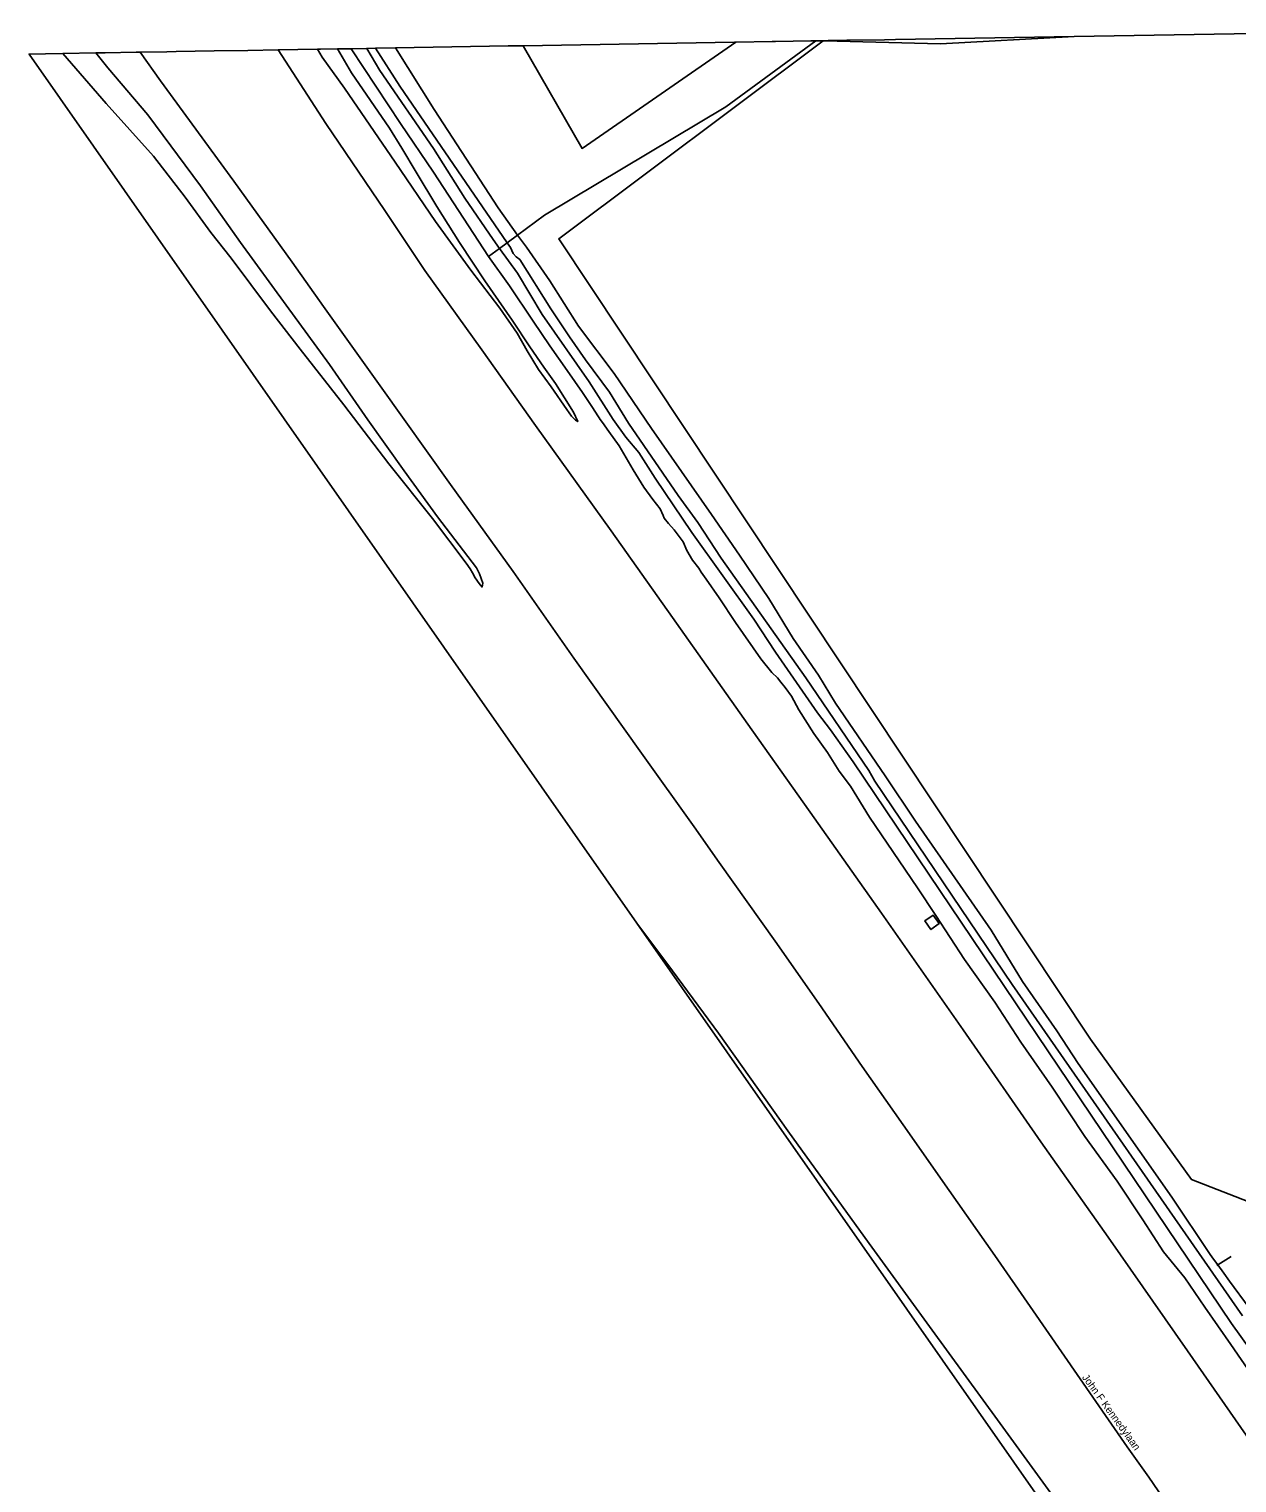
# Model space of a CAD drawing. Extents: x 161385 to 162589, y 388479 to 389756.
# Drawn here: x 161384.7 to 161547.5, y 389543.3 to 389739.2 of the extents above; entities that cross this region are included whole.
import ezdxf

# ---------------------------------------------------------------- set-up
doc = ezdxf.new("R2010")
doc.units = 0
for name, color, linetype in [('IMGEO_Berm_groen', 7, 'Continuous'), ('IMGEO_Bouwland', 7, 'Continuous'), ('IMGEO_Duiker', 7, 'Continuous'), ('IMGEO_Grasland_overig', 7, 'Continuous'), ('IMGEO_Groenvoorziening', 7, 'Continuous'), ('IMGEO_Loofbos', 7, 'Continuous'), ('IMGEO_Oever', 7, 'Continuous'), ('IMGEO_Openbare_ruimte_label', 7, 'Continuous'), ('IMGEO_Rijbaan_autoweg', 7, 'Continuous'), ('IMGEO_Sloot', 7, 'Continuous'), ('IMGEO_Terreindeel_gesloten', 7, 'Continuous'), ('IMGEO_Waterloop', 7, 'Continuous')]:
    doc.layers.add(name, color=color, linetype=linetype)

msp = doc.modelspace()

# ---------------------------------------------------------------- linework, layer by layer
at = {"layer": 'IMGEO_Berm_groen'}
for points in [[(161541.9, 389534.86), (161535.61, 389544.06), (161532.71, 389548.16), (161519.61, 389567.09), (161514.87, 389573.94), (161508.72, 389582.71), (161502.51, 389591.56), (161497, 389599.42), (161491.15, 389607.89), (161485.26, 389616.29), (161477.74, 389626.88), (161474.36, 389631.68), (161467.26, 389641.62), (161458.15, 389654.42), (161449.95, 389666.11), (161441.53, 389677.82), (161432.05, 389691.12), (161424.41, 389701.8), (161420.18, 389707.76), (161412.3, 389718.71), (161402.44, 389732.19), (161399.68, 389736.06), (161399.16, 389736.05), (161394.99, 389735.98), (161394.09, 389735.97), (161393.7, 389735.96), (161395.33, 389733.96), (161400.71, 389727.64), (161407.81, 389718.07), (161413.22, 389710.41), (161419.38, 389702), (161425.2, 389694), (161430.37, 389686.52), (161435.26, 389679.67), (161439.75, 389673.45), (161445.04, 389666.6), (161445.42, 389665.79), (161445.85, 389664.54), (161445.77, 389664.01), (161445.39, 389664.46), (161444.83, 389665.25), (161444.48, 389665.92), (161444.18, 389666.46), (161443.63, 389667.23), (161439.07, 389673.24), (161433.2, 389680.6), (161427.13, 389688.55), (161421.26, 389696.04), (161417.27, 389701.23), (161411.95, 389708.33), (161409.23, 389711.76), (161405.76, 389716.55), (161401.48, 389722.05), (161395.13, 389729.14), (161389.29, 389735.89), (161386.95, 389735.85), (161384.73, 389735.81), (161466.61, 389618.74), (161471.45, 389612.28), (161477.61, 389603.91), (161486.97, 389590.73), (161497.93, 389575.54), (161506.43, 389563.89), (161515.21, 389551.81), (161522.76, 389541.44)], [(161550.85, 389555.87), (161546.65, 389561.93), (161543.15, 389566.99), (161540.45, 389570.93), (161537.58, 389574.43), (161534.82, 389578.75), (161531.34, 389583.94), (161526.99, 389589.98), (161522.59, 389596.62), (161518.39, 389602.68), (161514.85, 389608.07), (161510.78, 389613.84), (161506.91, 389619.75), (161504.43, 389623.46), (161501.98, 389627.1), (161497.97, 389632.99), (161495.4, 389637.19), (161493.89, 389639.2), (161492.34, 389641.73), (161490.48, 389644.25), (161488.45, 389647.47), (161487.46, 389649.29), (161486.6, 389650.48), (161486.05, 389651.21), (161485.59, 389651.75), (161484.8, 389652.47), (161483.33, 389654.31), (161479.93, 389659.21), (161477.73, 389662.53), (161475.97, 389665.08), (161475.3, 389666), (161474.99, 389666.56), (161474.13, 389667.61), (161473.37, 389668.92), (161472.85, 389670.08), (161471.64, 389671.7), (161470.88, 389672.58), (161470.29, 389673.3), (161470.18, 389673.66), (161469.75, 389674.54), (161468.8, 389675.82), (161467.56, 389677.48), (161466.12, 389679.81), (161464.26, 389683.01), (161462.84, 389684.96), (161462, 389686.17), (161461.67, 389686.6), (161461.53, 389686.78), (161460.87, 389687.82), (161460.72, 389688.05), (161459.32, 389690.23), (161457.23, 389693.16), (161454.91, 389696.51), (161452.65, 389699.83), (161449.48, 389704.59), (161446.65, 389708.55), (161439.23, 389719.92), (161434.79, 389726.45), (161428.15, 389736.54), (161427.95, 389736.54), (161426.29, 389736.51), (161428.19, 389733.29), (161433.28, 389725.82), (161434.94, 389723.14), (161436.9, 389719.89), (161439.67, 389715.29), (161442.74, 389710.43), (161446.15, 389705.27), (161449.84, 389699.98), (161452.2, 389696.39), (161454.08, 389693.64), (161455.65, 389691.43), (161458.09, 389687.58), (161458.67, 389686.29), (161458.35, 389686.5), (161457.8, 389687.04), (161457.2, 389687.94), (161455.1, 389690.98), (161453.39, 389693.32), (161451.84, 389695.85), (161450.49, 389698.23), (161448.18, 389701.59), (161444.25, 389706.71), (161439.48, 389713.27), (161434.06, 389721.23), (161427.21, 389731.23), (161424.24, 389735.41), (161423.58, 389736.47), (161418.3, 389736.38), (161424.71, 389726.46), (161432.65, 389714.74), (161438.06, 389706.64), (161445.72, 389695.97), (161452.97, 389685.76), (161463.17, 389671.58), (161471.43, 389659.92), (161482.13, 389644.75), (161489.96, 389633.69), (161499.61, 389620.08), (161510.58, 389604.35), (161521.06, 389589.26), (161530.13, 389576.42), (161540.82, 389561.12), (161552.34, 389544.55)]]:
    msp.add_lwpolyline(points, dxfattribs=at)
msp.add_lwpolyline([(161507.36, 389618.66), (161506.25, 389617.86), (161505.43, 389619.01), (161506.55, 389619.8)], close=True, dxfattribs=at)
at = {"layer": 'IMGEO_Bouwland'}
msp.add_lwpolyline([(161479.95, 389737.41), (161459.25, 389723.11), (161451.31, 389736.93), (161479.8, 389737.41)], close=True, dxfattribs=at)
at = {"layer": 'IMGEO_Duiker'}
msp.add_lwpolyline([(161546.72, 389573.82), (161544.9, 389572.67), (161544.79, 389572.6)], dxfattribs=at)
at = {"layer": 'IMGEO_Grasland_overig'}
for points in [[(161393.7, 389735.96), (161389.29, 389735.89), (161395.13, 389729.14), (161401.48, 389722.05), (161405.76, 389716.55), (161409.23, 389711.76), (161411.95, 389708.33), (161417.27, 389701.23), (161421.26, 389696.04), (161427.13, 389688.55), (161433.2, 389680.6), (161439.07, 389673.24), (161443.63, 389667.23), (161444.18, 389666.46), (161444.48, 389665.92), (161444.83, 389665.25), (161445.39, 389664.46), (161445.77, 389664.01), (161445.85, 389664.54), (161445.42, 389665.79), (161445.04, 389666.6), (161439.75, 389673.45), (161435.26, 389679.67), (161430.37, 389686.52), (161425.2, 389694), (161419.38, 389702), (161413.22, 389710.41), (161407.81, 389718.07), (161400.71, 389727.64), (161395.33, 389733.96)], [(161426.29, 389736.51), (161424, 389736.47), (161423.58, 389736.47), (161424.24, 389735.41), (161427.21, 389731.23), (161434.06, 389721.23), (161439.48, 389713.27), (161444.25, 389706.71), (161448.18, 389701.59), (161450.49, 389698.23), (161451.84, 389695.85), (161453.39, 389693.32), (161455.1, 389690.98), (161457.2, 389687.94), (161457.8, 389687.04), (161458.35, 389686.5), (161458.67, 389686.29), (161458.09, 389687.58), (161455.65, 389691.43), (161454.08, 389693.64), (161452.2, 389696.39), (161449.84, 389699.98), (161446.15, 389705.27), (161442.74, 389710.43), (161439.67, 389715.29), (161436.9, 389719.89), (161434.94, 389723.14), (161433.28, 389725.82), (161428.19, 389733.29)]]:
    msp.add_lwpolyline(points, close=True, dxfattribs=at)
at = {"layer": 'IMGEO_Groenvoorziening'}
for points in [[(161479.95, 389737.41), (161484.88, 389737.5), (161485.31, 389737.51), (161490.08, 389737.59), (161490.75, 389737.6), (161478.64, 389728.7), (161454.18, 389714.09), (161450.56, 389711.43), (161447.94, 389715.08), (161439.3, 389728.36), (161434.12, 389736.64), (161449.29, 389736.9), (161451.31, 389736.93), (161459.25, 389723.11)], [(161491.86, 389737.61), (161492.4, 389737.62), (161494.92, 389737.67), (161500, 389737.75), (161501.46, 389737.78), (161525.54, 389738.18), (161507.54, 389737.18)]]:
    msp.add_lwpolyline(points, close=True, dxfattribs=at)
msp.add_lwpolyline([(161554.15, 389579.21), (161541.36, 389584.19), (161527.75, 389603.1), (161456.11, 389710.93), (161491.74, 389737.61), (161490.75, 389737.6), (161478.64, 389728.7), (161454.18, 389714.09), (161450.56, 389711.43), (161451.74, 389709.79), (161454.89, 389705.24), (161458.77, 389699.14), (161463.56, 389692.76), (161468.62, 389685.35), (161476.7, 389673.8), (161480.44, 389668.31), (161484.41, 389662.44), (161487.71, 389657.05), (161491.09, 389652.12), (161493.41, 389648.36), (161500.1, 389638.57), (161504.18, 389632.44), (161514.37, 389617.77), (161518.6, 389610.86), (161523.21, 389604.21), (161526.08, 389599.8), (161538.71, 389581.79), (161543.87, 389574.08), (161544.35, 389573.43), (161544.9, 389572.67), (161545.72, 389571.56), (161546.51, 389570.47), (161551.79, 389563.31)], dxfattribs=at)
at = {"layer": 'IMGEO_Loofbos'}
msp.add_lwpolyline([(161584.85, 389739.18), (161525.54, 389738.18), (161507.54, 389737.18), (161491.86, 389737.61), (161491.74, 389737.61), (161456.11, 389710.93), (161527.75, 389603.1), (161541.36, 389584.19), (161554.15, 389579.21)], dxfattribs=at)
at = {"layer": 'IMGEO_Oever'}
for points in [[(161428.15, 389736.54), (161434.79, 389726.45), (161439.23, 389719.92), (161446.65, 389708.55), (161448.12, 389709.63), (161447.25, 389710.82), (161443.45, 389716.42), (161439.21, 389723.09), (161431.97, 389733.62), (161430.22, 389736.58)], [(161434.12, 389736.64), (161431.41, 389736.6), (161434.7, 389731.47), (161449.14, 389710.38), (161450.56, 389711.43), (161447.94, 389715.08), (161439.3, 389728.36)]]:
    msp.add_lwpolyline(points, close=True, dxfattribs=at)
for points in [[(161551.79, 389563.31), (161546.51, 389570.47), (161545.72, 389571.56), (161544.9, 389572.67), (161544.35, 389573.43), (161543.87, 389574.08), (161538.71, 389581.79), (161526.08, 389599.8), (161523.21, 389604.21), (161518.6, 389610.86), (161514.37, 389617.77), (161504.18, 389632.44), (161500.1, 389638.57), (161493.41, 389648.36), (161491.09, 389652.12), (161487.71, 389657.05), (161484.41, 389662.44), (161480.44, 389668.31), (161476.7, 389673.8), (161468.62, 389685.35), (161463.56, 389692.76), (161458.77, 389699.14), (161454.89, 389705.24), (161451.74, 389709.79), (161450.56, 389711.43), (161449.14, 389710.38), (161449.58, 389709.73), (161449.95, 389708.96), (161450.37, 389708.49), (161450.84, 389708.13), (161455.04, 389701.47), (161457.54, 389697.73), (161459.69, 389694.61), (161462.94, 389690.24), (161465.48, 389686.08), (161472.21, 389676.35), (161474.85, 389672.68), (161478, 389667.88), (161489.42, 389651.78), (161497.88, 389639.28), (161498.7, 389637.87), (161517.22, 389610.46), (161548.23, 389565.82)], [(161552.02, 389557.47), (161546.75, 389564.77), (161495.78, 389640.45), (161492.73, 389644.75), (161490.99, 389647.04), (161485.32, 389655.24), (161482.37, 389659.66), (161474.04, 389671.34), (161469.1, 389678.66), (161466.88, 389682.11), (161465.13, 389684.21), (161463.45, 389686.57), (161460.21, 389691.67), (161453.88, 389700.72), (161450.56, 389706.29), (161448.12, 389709.63), (161446.65, 389708.55), (161449.48, 389704.59), (161452.65, 389699.83), (161454.91, 389696.51), (161457.23, 389693.16), (161459.32, 389690.23), (161460.72, 389688.05), (161460.87, 389687.82), (161461.53, 389686.78), (161461.67, 389686.6), (161462, 389686.17), (161462.84, 389684.96), (161464.26, 389683.01), (161466.12, 389679.81), (161467.56, 389677.48), (161468.8, 389675.82), (161469.75, 389674.54), (161470.18, 389673.66), (161470.29, 389673.3), (161470.88, 389672.58), (161471.64, 389671.7), (161472.85, 389670.08), (161473.37, 389668.92), (161474.13, 389667.61), (161474.99, 389666.56), (161475.3, 389666), (161475.97, 389665.08), (161477.73, 389662.53), (161479.93, 389659.21), (161483.33, 389654.31), (161484.8, 389652.47), (161485.59, 389651.75), (161486.05, 389651.21), (161486.6, 389650.48), (161487.46, 389649.29), (161488.45, 389647.47), (161490.48, 389644.25), (161492.34, 389641.73), (161493.89, 389639.2), (161495.4, 389637.19), (161497.97, 389632.99), (161501.98, 389627.1), (161504.43, 389623.46), (161506.91, 389619.75), (161510.78, 389613.84), (161514.85, 389608.07), (161518.39, 389602.68), (161522.59, 389596.62), (161526.99, 389589.98), (161531.34, 389583.94), (161534.82, 389578.75), (161537.58, 389574.43), (161540.45, 389570.93), (161543.15, 389566.99), (161546.65, 389561.93), (161550.85, 389555.87)]]:
    msp.add_lwpolyline(points, dxfattribs=at)
at = {"layer": 'IMGEO_Rijbaan_autoweg'}
for points in [[(161552.34, 389544.55), (161540.82, 389561.12), (161530.13, 389576.42), (161521.06, 389589.26), (161510.58, 389604.35), (161499.61, 389620.08), (161489.96, 389633.69), (161482.13, 389644.75), (161471.43, 389659.92), (161463.17, 389671.58), (161452.97, 389685.76), (161445.72, 389695.97), (161438.06, 389706.64), (161432.65, 389714.74), (161424.71, 389726.46), (161418.3, 389736.38), (161414.22, 389736.31), (161409.68, 389736.23), (161404.53, 389736.15), (161403.31, 389736.12), (161399.68, 389736.06), (161402.44, 389732.19), (161412.3, 389718.71), (161420.18, 389707.76), (161424.41, 389701.8), (161432.05, 389691.12), (161441.53, 389677.82), (161449.95, 389666.11), (161458.15, 389654.42), (161467.26, 389641.62), (161474.36, 389631.68), (161477.74, 389626.88), (161485.26, 389616.29), (161491.15, 389607.89), (161497, 389599.42), (161502.51, 389591.56), (161508.72, 389582.71), (161514.87, 389573.94), (161519.61, 389567.09), (161532.71, 389548.16), (161535.61, 389544.06), (161541.9, 389534.86)], [(161594.7, 389440.92), (161588.77, 389449.41), (161581.35, 389459.93), (161576.06, 389467.47), (161568.06, 389478.8), (161562.02, 389487.19), (161553.12, 389499.54), (161545.62, 389510.06), (161537.34, 389521.47), (161530.7, 389530.54), (161522.76, 389541.44), (161515.21, 389551.81), (161506.43, 389563.89), (161497.93, 389575.54), (161486.97, 389590.73), (161477.61, 389603.91), (161471.45, 389612.28), (161466.61, 389618.74), (161503, 389566.7), (161575.43, 389463.21), (161603.35, 389423.32)]]:
    msp.add_lwpolyline(points, dxfattribs=at)
at = {"layer": 'IMGEO_Sloot'}
msp.add_lwpolyline([(161431.41, 389736.6), (161430.22, 389736.58), (161431.97, 389733.62), (161439.21, 389723.09), (161443.45, 389716.42), (161447.25, 389710.82), (161448.12, 389709.63), (161449.14, 389710.38), (161434.7, 389731.47)], close=True, dxfattribs=at)
at = {"layer": 'IMGEO_Terreindeel_gesloten'}
msp.add_lwpolyline([(161506.55, 389619.8), (161505.43, 389619.01), (161506.25, 389617.86), (161507.36, 389618.66)], close=True, dxfattribs=at)
at = {"layer": 'IMGEO_Waterloop'}
msp.add_lwpolyline([(161548.23, 389565.82), (161517.22, 389610.46), (161498.7, 389637.87), (161497.88, 389639.28), (161489.42, 389651.78), (161478, 389667.88), (161474.85, 389672.68), (161472.21, 389676.35), (161465.48, 389686.08), (161462.94, 389690.24), (161459.69, 389694.61), (161457.54, 389697.73), (161455.04, 389701.47), (161450.84, 389708.13), (161450.37, 389708.49), (161449.95, 389708.96), (161449.58, 389709.73), (161449.14, 389710.38), (161448.12, 389709.63), (161450.56, 389706.29), (161453.88, 389700.72), (161460.21, 389691.67), (161463.45, 389686.57), (161465.13, 389684.21), (161466.88, 389682.11), (161469.1, 389678.66), (161474.04, 389671.34), (161482.37, 389659.66), (161485.32, 389655.24), (161490.99, 389647.04), (161492.73, 389644.75), (161495.78, 389640.45), (161546.75, 389564.77), (161552.02, 389557.47)], dxfattribs=at)

# ---------------------------------------------------------------- texts
at = {"layer": 'IMGEO_Openbare_ruimte_label'}
msp.add_text('John F Kennedylaan', height=1, rotation=305.9642, dxfattribs=at).set_placement((161526.57, 389557.51))

doc.saveas('drawing.dxf')
